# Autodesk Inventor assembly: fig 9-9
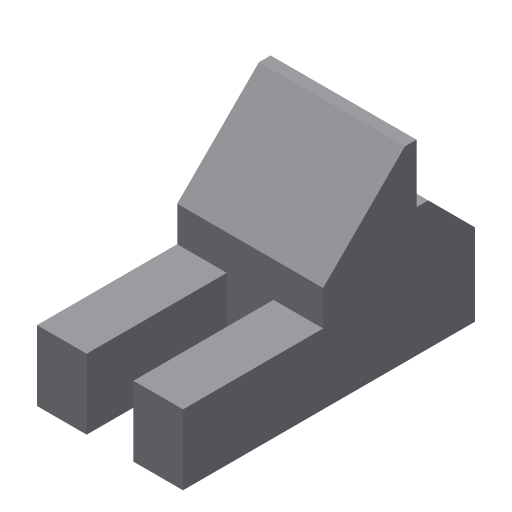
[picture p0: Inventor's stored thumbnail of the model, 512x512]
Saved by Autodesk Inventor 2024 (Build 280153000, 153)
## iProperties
Shininess: 64.0
Length Units: 11269
Angle Units: 11279
Time Units: 11290
Mass Units: 11283
Length Display Precision: 3
Angle Display Precision: 2
Created: 2002-01
Part Number: fig 9-9
Document SubType Name: Assembly
Designer: ***
Density: 0.0
Volumn: 0.0
Area: 0.0
PropertySet Name: Model Information
Control State: 0
Master: False
Checked Out: False
Author: ***
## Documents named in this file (3)
- D:\PROJECTS\Project 2023\RESOURCES INVENTOR 2024\RESOURCES INVENTOR 2024\Inventor_2023_Part\Inventor_2024_Part\c09_Inv_2024_prt\fig 9-9.iam
- D:\PROJECTS\Project 2023\RESOURCES INVENTOR 2024\RESOURCES INVENTOR 2024\Inventor_2023_Part\Inventor_2024_Part\c09_Inv_2024_prt\Part3.ipt
- D:\PROJECTS\Project 2023\RESOURCES INVENTOR 2024\RESOURCES INVENTOR 2024\Inventor_2023_Part\Inventor_2024_Part\c09_Inv_2024_prt\Part4.ipt
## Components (2 placed, 2 different names)
1. Part3:1 — Mate:1
2. Part4:1 — Mate:1
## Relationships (1: Mate 1)
- Mate:1: Part3:1 ↔ Part4:1
